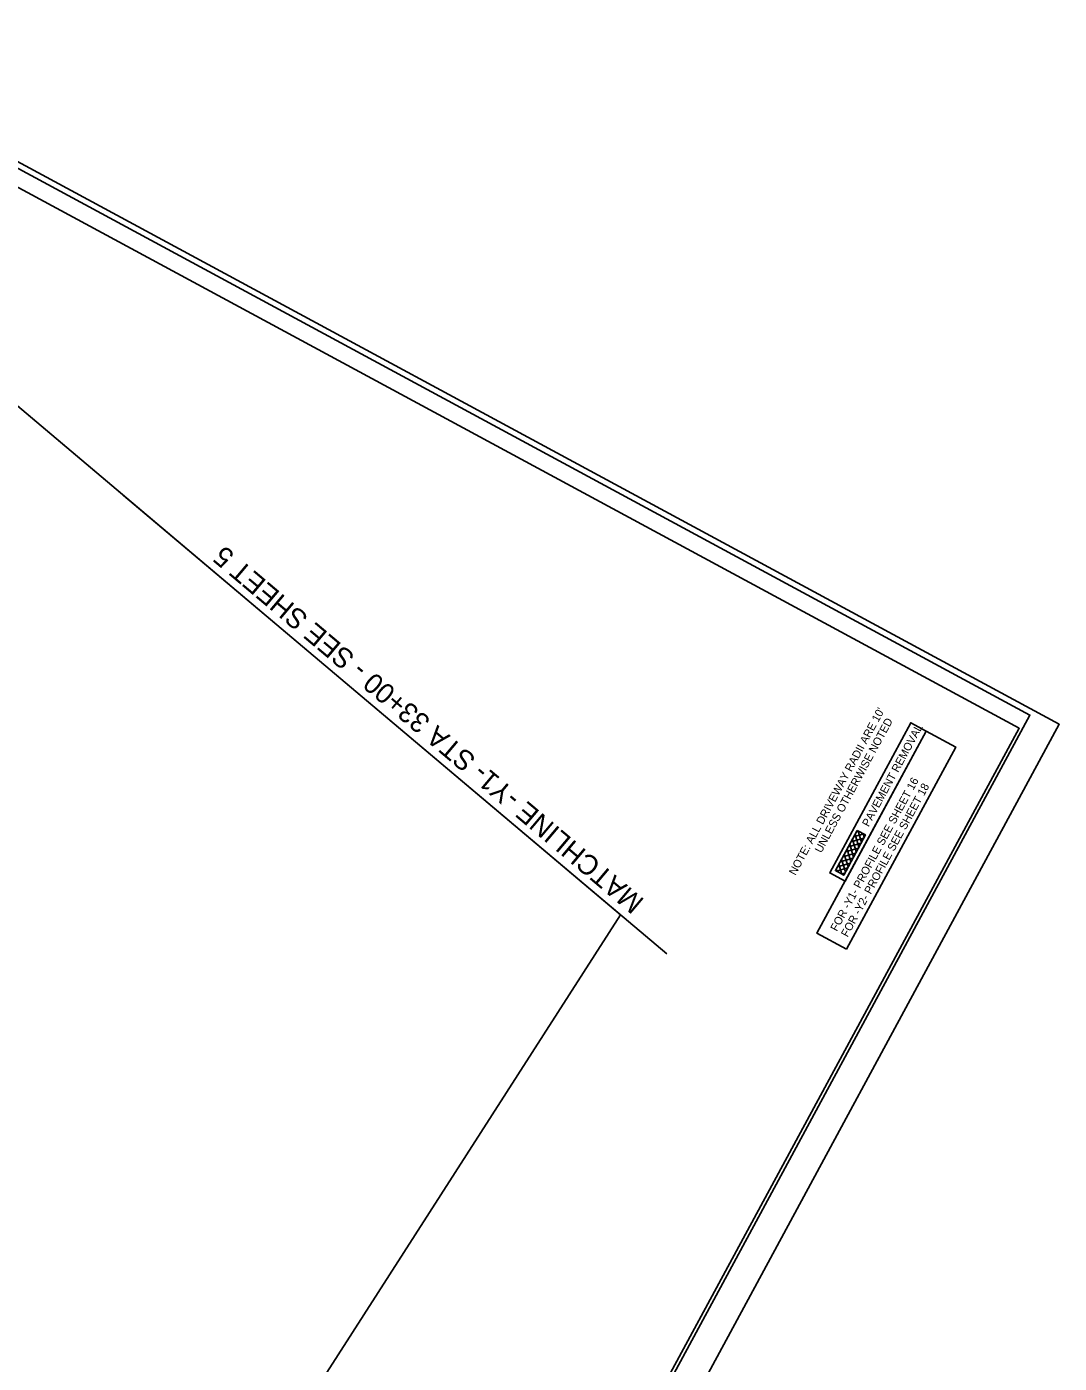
# Model space of a CAD drawing. Extents: x 2345885 to 2347654, y 842598 to 844603.
# Drawn here: x 2346880 to 2347654, y 843601 to 844603 of the extents above; entities that cross this region are included whole.
import ezdxf

# ---------------------------------------------------------------- set-up
doc = ezdxf.new("R2010")
doc.units = 0
for name, color, linetype in [('Default', 7, 'Continuous'), ('Matchline', 7, 'Continuous'), ('Matchline Text', 7, 'Continuous'), ('Prop DSN Text', 7, 'Continuous'), ('Prop PFL Text', 7, 'Continuous'), ('Sheet Border Standard 30in CELL', 7, 'Continuous'), ('Sheet Clip Boundary CELL', 7, 'Continuous'), ('Sheet Plot Border Inside CELL', 7, 'Continuous'), ('Sheet Plot Border Outside CELL', 7, 'Continuous')]:
    doc.layers.add(name, color=color, linetype=linetype)

msp = doc.modelspace()

# ---------------------------------------------------------------- linework, layer by layer
at = {"layer": 'Default'}
for p, q in [((2347499.4, 843995.4), (2347507, 843997.6)), ((2347503.4, 843987.8), (2347500.5, 843997.3)), ((2347501.5, 843999.1), (2347503.3, 843999.6)), ((2347505.4, 843991.5), (2347502.9, 843999.8)), ((2347507.4, 843995.3), (2347506.6, 843997.8)), ((2347493.4, 843984.2), (2347502.9, 843987)), ((2347497.3, 843976.6), (2347494.5, 843986.1)), ((2347495.4, 843987.9), (2347505, 843990.7)), ((2347499.3, 843980.3), (2347496.5, 843989.9)), ((2347497.4, 843991.6), (2347507, 843994.5)), ((2347501.3, 843984.1), (2347498.5, 843993.6)), ((2347487.3, 843973), (2347496.9, 843975.8)), ((2347489.4, 843976.7), (2347498.9, 843979.5)), ((2347493.3, 843969.1), (2347490.4, 843978.7)), ((2347491.4, 843980.4), (2347500.9, 843983.3)), ((2347495.3, 843972.9), (2347492.4, 843982.4)), ((2347486.9, 843969.5), (2347486.4, 843971.2)), ((2347486.7, 843969.6), (2347494.9, 843972.1)), ((2347490.6, 843967.5), (2347488.4, 843974.9)), ((2347490.4, 843967.6), (2347492.8, 843968.3))]:
    msp.add_line(p, q, dxfattribs=at)
for points in [[(2347493, 843962.2), (2347553.8, 844074.8), (2347542.3, 844081), (2347481.5, 843968.4)], [(2347502.1, 844000.3), (2347485.8, 843970.1), (2347492, 843966.7), (2347508.3, 843996.9)]]:
    msp.add_lwpolyline(points, close=True, dxfattribs=at)
at = {"layer": 'Matchline'}
msp.add_lwpolyline([(2347359.5, 843907.6), (2346952.4, 844251.3), (2346952.4, 844251.3), (2346952.4, 844251.3)], dxfattribs=at)
at = {"layer": 'Prop PFL Text'}
msp.add_lwpolyline([(2347494.1, 843911.1), (2347576, 844062.7), (2347553.8, 844074.8), (2347471.9, 843923.1)], close=True, dxfattribs=at)
at = {"layer": 'Sheet Border Standard 30in CELL'}
msp.add_lwpolyline([(2346699.7, 844576.1), (2345986.6, 843256.5), (2346910.3, 842757.3), (2347623.5, 844076.9)], close=True, dxfattribs=at)
at = {"layer": 'Sheet Clip Boundary CELL'}
for points in [[(2346122.3, 843455.1), (2346122.3, 843455.1), (2346122.3, 843455.1), (2346732, 842882), (2346732, 842882), (2346732, 842882), (2346732, 842882), (2346732, 842882), (2346843.6, 842821.7), (2347080.7, 843191.4), (2347008.6, 843443.9), (2347008.6, 843443.9), (2347324.8, 843936.9), (2347067.3, 844154.3), (2346803.6, 844377), (2346803.6, 844377), (2346762.9, 844301.7), (2346621.3, 844378.3)], [(2346122.3, 843455.1), (2346122.3, 843455.1), (2346122.3, 843455.1), (2346732, 842882), (2346732, 842882), (2346732, 842882), (2346732, 842882), (2346732, 842882), (2346843.6, 842821.7), (2347088.8, 843163), (2347008.6, 843443.9), (2347008.6, 843443.9), (2347324.8, 843936.9), (2347067.3, 844154.3), (2346838.9, 844347.2), (2346838.9, 844347.2), (2346582.5, 843745.3), (2346345.2, 843867.4)]]:
    msp.add_lwpolyline(points, close=True, dxfattribs=at)
at = {"layer": 'Sheet Plot Border Inside CELL'}
msp.add_lwpolyline([(2346703.4, 844588.3), (2345911.1, 843122.2), (2346839.3, 842620.6), (2347631.6, 844086.7)], close=True, dxfattribs=at)
at = {"layer": 'Sheet Plot Border Outside CELL'}
msp.add_lwpolyline([(2346685.8, 844602.9), (2345885.2, 843121.4), (2346852.9, 842598.4), (2347653.5, 844079.9)], close=True, dxfattribs=at)

# ---------------------------------------------------------------- texts
at = {"layer": 'Matchline Text'}
msp.add_text('MATCHLINE -Y1- STA 33+00 - SEE SHEET 5', height=15, rotation=139.8208, dxfattribs=at).set_placement((2347343.3, 843948.1))
at = {"layer": 'Prop DSN Text'}
for s, p in [("NOTE: ALL DRIVEWAY RADII ARE 10' ", (2347455.8, 843966.1)), ('UNLESS OTHERWISE NOTED', (2347475.2, 843982.9)), ('PAVEMENT REMOVAL', (2347510.7, 844002.5)), ('FOR -Y1- PROFILE SEE SHEET 16', (2347486.9, 843924.1)), ('FOR -Y2- PROFILE SEE SHEET 18', (2347494.9, 843919.8))]:
    msp.add_text(s, height=6, rotation=61.6124, dxfattribs=at).set_placement(p)

doc.saveas('drawing.dxf')
